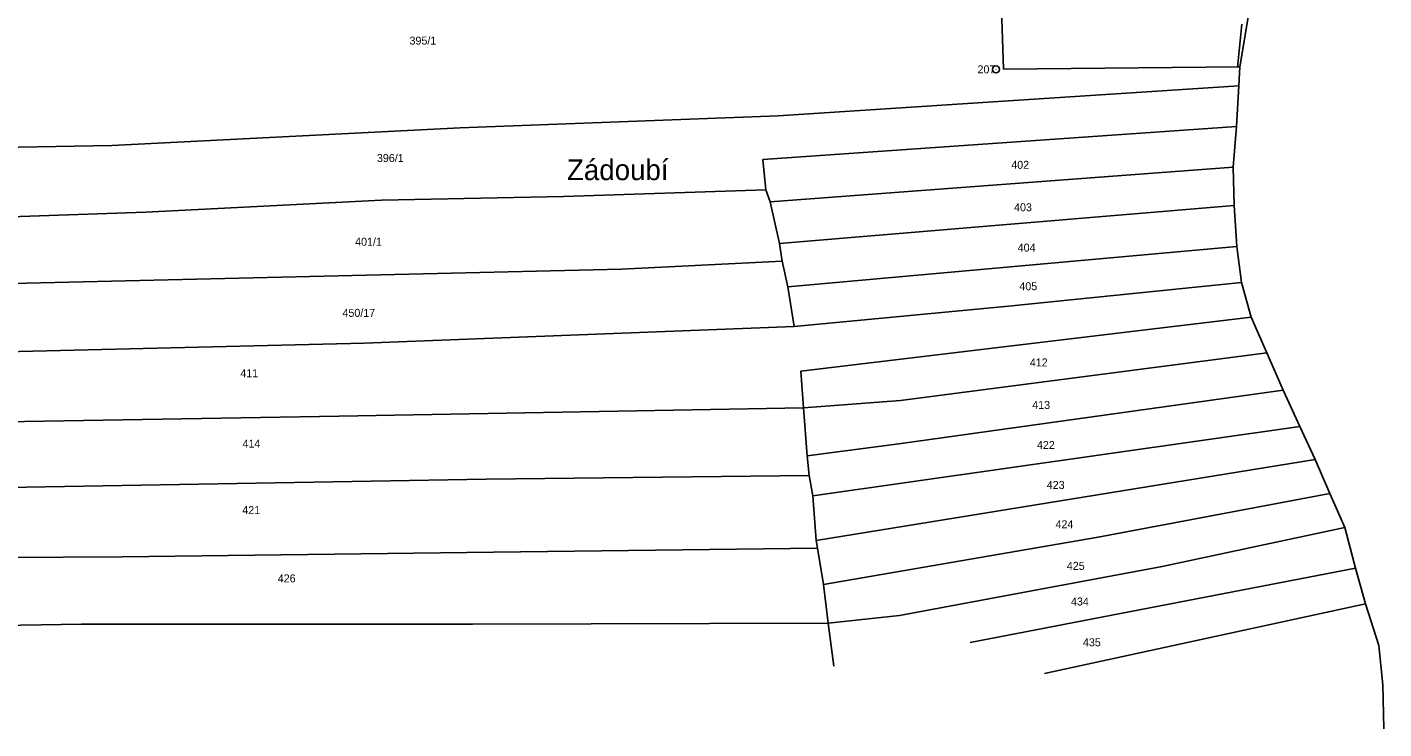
# Model space of a CAD drawing. Extents: x -747333 to -745433, y -1133152 to -1130600.
# Drawn here: x -746069.1 to -745780.8, y -1132646.5 to -1132497.4 of the extents above; entities that cross this region are included whole.
import ezdxf

# ---------------------------------------------------------------- set-up
doc = ezdxf.new("R2010")
doc.units = 0
for name, color, linetype in [('Vrstva 1', 7, 'Continuous'), ('Vrstva 15', 7, 'Continuous'), ('Vrstva 17', 7, 'Continuous'), ('Vrstva 18', 7, 'Continuous'), ('Vrstva 24', 7, 'Continuous'), ('Vrstva 52', 7, 'Continuous'), ('Vrstva 6', 7, 'Continuous')]:
    doc.layers.add(name, color=color, linetype=linetype)

msp = doc.modelspace()

# ---------------------------------------------------------------- linework, layer by layer
at = {"layer": 'Vrstva 1'}
for points in [[(-745862.5, -1132480.64), (-745861.7, -1132506.3)], [(-745811.43, -1132505.81), (-745809.68, -1132495.27)], [(-745861.7, -1132506.3), (-745811.43, -1132505.81)], [(-745811.43, -1132505.81), (-745811.67, -1132509.89)], [(-745811.67, -1132509.89), (-745812.17, -1132518.54)], [(-745812.17, -1132518.54), (-745812.83, -1132527.16)], [(-745812.83, -1132527.16), (-745812.67, -1132535.31)], [(-745812.67, -1132535.31), (-745812.06, -1132543.98)], [(-745812.06, -1132543.98), (-745811.08, -1132551.63)], [(-745811.08, -1132551.63), (-745809.01, -1132559.05)], [(-745809.01, -1132559.05), (-745805.72, -1132566.58)], [(-745805.72, -1132566.58), (-745802.24, -1132574.56)], [(-745802.24, -1132574.56), (-745798.7, -1132582.27)], [(-745798.7, -1132582.27), (-745795.47, -1132589.3)], [(-745795.47, -1132589.3), (-745792.31, -1132596.5)], [(-745792.31, -1132596.5), (-745789.14, -1132603.72)], [(-745789.14, -1132603.72), (-745786.85, -1132612.35)], [(-745786.85, -1132612.35), (-745784.77, -1132619.99)], [(-745784.77, -1132619.99), (-745781.9, -1132628.79)]]:
    msp.add_lwpolyline(points, dxfattribs=at)
at = {"layer": 'Vrstva 24'}
msp.add_line((-745863.31, -1132506.36), (-745863.21, -1132506.36), dxfattribs=at)
msp.add_circle((-745863.26, -1132506.36), 0.756017, dxfattribs=at)
at = {"layer": 'Vrstva 52'}
msp.add_lwpolyline([(-745780.84, -1132646.53), (-745781.06, -1132637.14), (-745781.9, -1132628.79), (-745784.77, -1132619.99), (-745786.85, -1132612.35), (-745789.14, -1132603.72), (-745792.31, -1132596.5), (-745795.47, -1132589.3), (-745798.7, -1132582.27), (-745802.24, -1132574.56), (-745805.72, -1132566.58), (-745809.01, -1132559.05), (-745811.08, -1132551.63), (-745812.06, -1132543.98), (-745812.67, -1132535.31), (-745812.83, -1132527.16), (-745812.17, -1132518.54), (-745811.67, -1132509.89), (-745811.43, -1132505.81), (-745811.9, -1132505.82), (-745811.88, -1132505.25), (-745811, -1132496.75)], dxfattribs=at)
at = {"layer": 'Vrstva 6'}
for points in [[(-745909.55, -1132516.26), (-745811.67, -1132509.89)], [(-745977.09, -1132518.81), (-745909.55, -1132516.26)], [(-746051.11, -1132522.54), (-745977.09, -1132518.81)], [(-745912.79, -1132525.5), (-745812.17, -1132518.54)], [(-746110.56, -1132523.64), (-746051.11, -1132522.54)], [(-745912.2, -1132531.98), (-745912.79, -1132525.5)], [(-745911.23, -1132534.53), (-745812.83, -1132527.16)], [(-745955.19, -1132533.35), (-745912.2, -1132531.98)], [(-745912.2, -1132531.98), (-745911.23, -1132534.53)], [(-746043.93, -1132536.69), (-745993.87, -1132534.14)], [(-745993.87, -1132534.14), (-745955.19, -1132533.35)], [(-745911.23, -1132534.53), (-745909.26, -1132543.37)], [(-746126.21, -1132539.52), (-746043.93, -1132536.69)], [(-745909.26, -1132543.37), (-745812.67, -1132535.31)], [(-745909.26, -1132543.37), (-745908.67, -1132547.1)], [(-745907.5, -1132552.6), (-745812.06, -1132543.98)], [(-746087.42, -1132552.21), (-745942.83, -1132548.86)], [(-745908.67, -1132547.1), (-745942.83, -1132548.86)], [(-745908.67, -1132547.1), (-745907.5, -1132552.6)], [(-745860.58, -1132556.72), (-745811.08, -1132551.63)], [(-745907.5, -1132552.6), (-745906.12, -1132561.04)], [(-745906.12, -1132561.04), (-745860.58, -1132556.72)], [(-745997.5, -1132564.58), (-745906.12, -1132561.04)], [(-745809.01, -1132559.05), (-745904.75, -1132570.47)], [(-746155.97, -1132568.38), (-745997.5, -1132564.58)], [(-745883.55, -1132576.75), (-745805.72, -1132566.58)], [(-745904.75, -1132570.47), (-745904.16, -1132578.32)], [(-745883.94, -1132585.98), (-745802.24, -1132574.56)], [(-746002.81, -1132580.09), (-745904.16, -1132578.32)], [(-745904.16, -1132578.32), (-745883.55, -1132576.75)], [(-745904.16, -1132578.32), (-745903.37, -1132588.53)], [(-746145.08, -1132582.47), (-746002.81, -1132580.09)], [(-745902.2, -1132596.98), (-745798.7, -1132582.27)], [(-745903.37, -1132588.53), (-745883.94, -1132585.98)], [(-745903.37, -1132588.53), (-745902.98, -1132592.66)], [(-745901.46, -1132606.5), (-745795.47, -1132589.3)], [(-745971.59, -1132593.45), (-745902.98, -1132592.66)], [(-745902.98, -1132592.66), (-745902.2, -1132596.98)], [(-746134.56, -1132596.27), (-745971.59, -1132593.45)], [(-745902.2, -1132596.98), (-745901.46, -1132606.5)], [(-745841.58, -1132605.81), (-745792.31, -1132596.5)], [(-745827.94, -1132611.99), (-745789.14, -1132603.72)], [(-745901.46, -1132606.5), (-745901.19, -1132608.09)], [(-745899.89, -1132615.82), (-745841.58, -1132605.81)], [(-746124.42, -1132610.4), (-746048.94, -1132609.94)], [(-746048.94, -1132609.94), (-745970.02, -1132608.96)], [(-745970.02, -1132608.96), (-745901.19, -1132608.09)], [(-745901.19, -1132608.09), (-745899.89, -1132615.82)], [(-745883.79, -1132622.4), (-745827.94, -1132611.99)], [(-745868.77, -1132628.2), (-745786.85, -1132612.35)], [(-745899.89, -1132615.82), (-745898.91, -1132624.07)], [(-745852.97, -1132634.77), (-745784.77, -1132619.99)], [(-746113.57, -1132625.23), (-746057.58, -1132624.28)], [(-746057.58, -1132624.28), (-745974.53, -1132624.28)], [(-745974.53, -1132624.28), (-745898.91, -1132624.07)], [(-745898.91, -1132624.07), (-745883.79, -1132622.4)], [(-745898.91, -1132624.07), (-745897.73, -1132633.2)]]:
    msp.add_lwpolyline(points, dxfattribs=at)

# ---------------------------------------------------------------- texts
at = {"layer": 'Vrstva 15'}
msp.add_text('Zádoubí', height=4.4, dxfattribs=at).set_placement((-745954.4256, -1132529.91))
at = {"layer": 'Vrstva 17'}
msp.add_text('207', height=1.7, dxfattribs=at).set_placement((-745867.188954, -1132507.21))
at = {"layer": 'Vrstva 18'}
for s, p in [('395/1', (-745987.88, -1132501.1)), ('396/1', (-745994.81, -1132526.05)), ('402', (-745860.01, -1132527.5)), ('403', (-745859.42, -1132536.52)), ('401/1', (-745999.44, -1132543.84)), ('404', (-745858.65, -1132545.09)), ('405', (-745858.3, -1132553.3)), ('450/17', (-746002.13, -1132558.96)), ('412', (-745856.07, -1132569.5)), ('411', (-746023.84, -1132571.81)), ('413', (-745855.56, -1132578.54)), ('414', (-746023.36, -1132586.73)), ('422', (-745854.56, -1132587.04)), ('423', (-745852.47, -1132595.54)), ('421', (-746023.42, -1132600.87)), ('424', (-745850.62, -1132603.9)), ('425', (-745848.21, -1132612.73)), ('426', (-746015.88, -1132615.4)), ('434', (-745847.33, -1132620.31)), ('435', (-745844.79, -1132628.98))]:
    msp.add_text(s, height=1.7, dxfattribs=at).set_placement(p)

doc.saveas('drawing.dxf')
